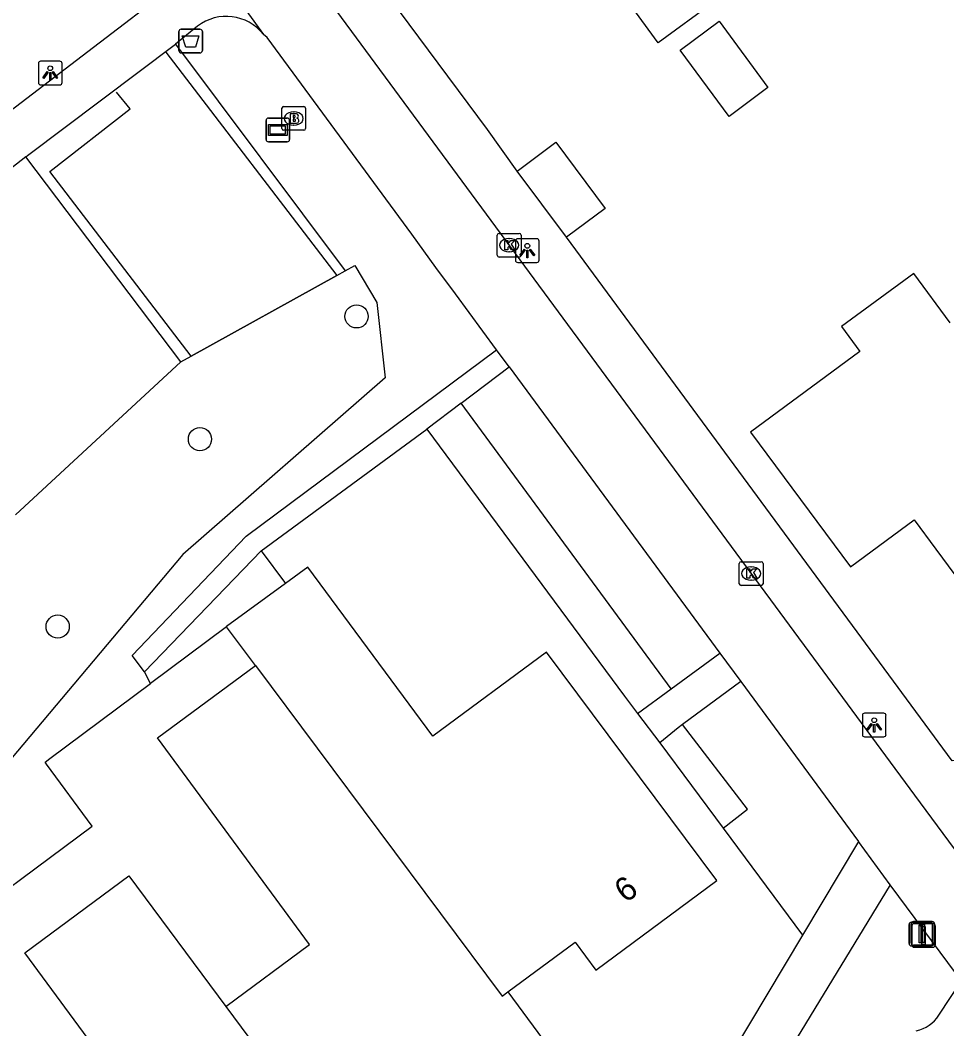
# Model space of a CAD drawing. Extents: x 163427 to 164190, y 380331 to 381641.
# Drawn here: x 163878.34 to 163917.37, y 381059.16 to 381101.66 of the extents above; entities that cross this region are included whole.
import ezdxf

# ---------------------------------------------------------------- set-up
doc = ezdxf.new("R2010")
doc.units = 0
for name, color, linetype in [('IMGEO_Afsluitpaal', 7, 'Continuous'), ('IMGEO_Afvalbak', 7, 'Continuous'), ('IMGEO_Boom', 7, 'Continuous'), ('IMGEO_Brandkraan', 7, 'Continuous'), ('IMGEO_Fietspad_open', 7, 'Continuous'), ('IMGEO_Groenvoorziening', 7, 'Continuous'), ('IMGEO_Hek', 7, 'Continuous'), ('IMGEO_Kolk', 7, 'Continuous'), ('IMGEO_Lichtpunt', 7, 'Continuous'), ('IMGEO_Muur', 7, 'Continuous'), ('IMGEO_Pand', 7, 'Continuous'), ('IMGEO_Pand_nummerreeks', 7, 'Continuous'), ('IMGEO_Verklikker', 7, 'Continuous'), ('IMGEO_Voetpad_halfverhard', 7, 'Continuous'), ('IMGEO_Voetpad_open', 7, 'Continuous')]:
    doc.layers.add(name, color=color, linetype=linetype)

msp = doc.modelspace()

# ---------------------------------------------------------------- linework, layer by layer
at = {"layer": 'IMGEO_Afsluitpaal'}
for p, q in [((163915.959, 381063.681), (163916.749, 381063.681)), ((163916.749, 381063.681), (163915.959, 381063.681)), ((163915.778, 381062.756), (163915.778, 381063.556)), ((163915.778, 381063.556), (163915.778, 381062.756)), ((163915.859, 381062.781), (163915.859, 381063.581)), ((163915.859, 381063.581), (163915.859, 381062.781)), ((163915.878, 381063.656), (163916.668, 381063.656)), ((163916.668, 381063.656), (163915.878, 381063.656)), ((163915.887, 381062.696), (163915.887, 381063.496)), ((163915.887, 381063.496), (163915.887, 381062.696)), ((163915.987, 381063.596), (163916.777, 381063.596)), ((163916.777, 381063.596), (163915.987, 381063.596)), ((163916.768, 381063.556), (163916.768, 381062.756)), ((163916.768, 381062.756), (163916.768, 381063.556)), ((163916.849, 381063.581), (163916.849, 381062.781)), ((163916.849, 381062.781), (163916.849, 381063.581)), ((163916.877, 381063.496), (163916.877, 381062.696)), ((163916.877, 381062.696), (163916.877, 381063.496)), ((163916.668, 381062.656), (163915.878, 381062.656)), ((163915.878, 381062.656), (163916.668, 381062.656)), ((163916.749, 381062.681), (163915.959, 381062.681)), ((163915.959, 381062.681), (163916.749, 381062.681)), ((163916.777, 381062.596), (163915.987, 381062.596)), ((163915.987, 381062.596), (163916.777, 381062.596))]:
    msp.add_line(p, q, dxfattribs=at)
for points in [[(163916.198, 381063.531), (163916.348, 381063.531), (163916.348, 381062.781), (163916.198, 381062.781), (163916.198, 381063.531)], [(163916.279, 381063.556), (163916.429, 381063.556), (163916.429, 381062.806), (163916.279, 381062.806), (163916.279, 381063.556)], [(163916.307, 381063.471), (163916.457, 381063.471), (163916.457, 381062.721), (163916.307, 381062.721), (163916.307, 381063.471)]]:
    msp.add_lwpolyline(points, dxfattribs=at)
for centre, start, end in [((163915.959, 381063.581), 90, 180), ((163915.959, 381063.581), 90, 180), ((163916.749, 381063.581), 0, 90), ((163916.749, 381063.581), 360, 90), ((163915.878, 381063.556), 90, 180), ((163915.878, 381063.556), 90, 180), ((163915.987, 381063.496), 90, 180), ((163915.987, 381063.496), 90, 180), ((163916.668, 381063.556), 0, 90), ((163916.668, 381063.556), 360, 90), ((163916.777, 381063.496), 0, 90), ((163916.777, 381063.496), 360, 90), ((163915.878, 381062.756), 180, 270), ((163915.878, 381062.756), 180, 270), ((163915.959, 381062.781), 180, 270), ((163915.959, 381062.781), 180, 270), ((163915.987, 381062.696), 180, 270), ((163915.987, 381062.696), 180, 270), ((163916.668, 381062.756), 270, 0), ((163916.668, 381062.756), 270, 0), ((163916.749, 381062.781), 270, 0), ((163916.749, 381062.781), 270, 0), ((163916.777, 381062.696), 270, 0), ((163916.777, 381062.696), 270, 0)]:
    msp.add_arc(centre, 0.1, start, end, dxfattribs=at)
at = {"layer": 'IMGEO_Afvalbak'}
for p, q in [((163885.023, 381100.383), (163885.023, 381101.183)), ((163885.023, 381101.183), (163885.023, 381100.383)), ((163885.123, 381101.283), (163885.913, 381101.283)), ((163885.913, 381101.283), (163885.123, 381101.283)), ((163886.013, 381101.183), (163886.013, 381100.383)), ((163886.013, 381100.383), (163886.013, 381101.183)), ((163885.913, 381100.283), (163885.123, 381100.283)), ((163885.123, 381100.283), (163885.913, 381100.283))]:
    msp.add_line(p, q, dxfattribs=at)
msp.add_lwpolyline([(163885.166, 381100.997), (163885.87, 381100.997), (163885.721, 381100.527), (163885.315, 381100.527), (163885.166, 381100.997)], dxfattribs=at)
for centre, start, end in [((163885.123, 381101.183), 90, 180), ((163885.123, 381101.183), 90, 180), ((163885.913, 381101.183), 0, 90), ((163885.913, 381101.183), 360, 90), ((163885.123, 381100.383), 180, 270), ((163885.123, 381100.383), 180, 270), ((163885.913, 381100.383), 270, 0), ((163885.913, 381100.383), 270, 0)]:
    msp.add_arc(centre, 0.1, start, end, dxfattribs=at)
at = {"layer": 'IMGEO_Boom'}
for centre in [(163892.507, 381089.182), (163885.912, 381084.008), (163879.92, 381076.111)]:
    msp.add_circle(centre, 0.489, dxfattribs=at)
at = {"layer": 'IMGEO_Brandkraan'}
for p, q in [((163889.361, 381097.097), (163889.361, 381097.949)), ((163889.436, 381098.023), (163890.288, 381098.023)), ((163889.849, 381097.803), (163889.874, 381097.803)), ((163890.362, 381097.949), (163890.362, 381097.097)), ((163889.872, 381097.243), (163889.847, 381097.243)), ((163890.288, 381097.023), (163889.436, 381097.023))]:
    msp.add_line(p, q, dxfattribs=at)
for points in [[(163889.361, 381097.097), (163889.361, 381097.949)], [(163889.436, 381098.023), (163890.288, 381098.023)], [(163889.709, 381097.723), (163889.709, 381097.323), (163889.922, 381097.323)], [(163889.94, 381097.723), (163889.709, 381097.723)], [(163890.362, 381097.949), (163890.362, 381097.097)], [(163889.888, 381097.642), (163889.834, 381097.642), (163889.834, 381097.566)], [(163889.834, 381097.566), (163889.887, 381097.566)], [(163889.896, 381097.49), (163889.834, 381097.49), (163889.834, 381097.409)], [(163889.834, 381097.409), (163889.896, 381097.409)], [(163890.288, 381097.023), (163889.436, 381097.023)]]:
    msp.add_lwpolyline(points, dxfattribs=at)
for centre, radius, start, end in [((163889.438, 381097.947), 0.0765, 91.552, 178.448), ((163889.438, 381097.947), 0.0765, 91.552, 178.448), ((163889.944, 381097.578), 0.145, 59.4692, 91.5367), ((163889.969, 381097.625), 0.0922, 285.5137, 58.1501), ((163890.286, 381097.947), 0.0765, 1.552, 88.448), ((163890.286, 381097.947), 0.0765, 1.552, 88.448), ((163889.889, 381097.604), 0.0379, 267.8285, 90.9355), ((163889.897, 381097.449), 0.0404, 269.8759, 90.5077), ((163889.928, 381097.574), 0.251, 268.6676, 293.5347), ((163889.974, 381097.433), 0.105, 301.3115, 78.989), ((163889.438, 381097.099), 0.0765, 181.552, 268.448), ((163889.438, 381097.099), 0.0765, 181.552, 268.448), ((163890.286, 381097.099), 0.0765, 271.552, 358.448), ((163890.286, 381097.099), 0.0765, 271.552, 358.448)]:
    msp.add_arc(centre, radius, start, end, dxfattribs=at)
for centre, major_axis, ratio, start_param, end_param in [((163889.848, 381097.523), (-0.387, 0.002), 0.722429, 4.712389, 7.853982), ((163889.873, 381097.523), (-0.39, 0.002), 0.717154, 1.570796, 4.712389)]:
    msp.add_ellipse(centre, major_axis=major_axis, ratio=ratio, start_param=start_param, end_param=end_param, dxfattribs=at)
at = {"layer": 'IMGEO_Fietspad_open'}
for points in [[(163879.294, 381118.846), (163916.003, 381069.011), (163920.063, 381063.521)], [(163885.203, 381105.739), (163888.584, 381101.063)], [(163898.402, 381087.778), (163896.67, 381090.133), (163895.849, 381091.249), (163894.831, 381092.652), (163888.737, 381100.935), (163888.584, 381101.063)], [(163898.929, 381087.061), (163898.402, 381087.778)], [(163898.929, 381087.061), (163907.808, 381074.986)], [(163907.808, 381074.986), (163908.685, 381073.793)], [(163908.685, 381073.793), (163913.644, 381067.049)], [(163914.985, 381065.235), (163913.644, 381067.049)], [(163917.772, 381061.459), (163914.985, 381065.235)]]:
    msp.add_lwpolyline(points, dxfattribs=at)
at = {"layer": 'IMGEO_Groenvoorziening'}
for points in [[(163884.881, 381100.649), (163892.032, 381091.103)], [(163885.102, 381087.269), (163878.573, 381095.902)], [(163892.032, 381091.103), (163892.433, 381091.325), (163893.363, 381089.769), (163893.712, 381086.589), (163885.188, 381079.149), (163877.401, 381069.894), (163877.35, 381068.327), (163876.539, 381066.473), (163872.253, 381063.156), (163871.244, 381061.59), (163871.684, 381058.886), (163871, 381056.23), (163869.868, 381054.37), (163867.112, 381051.126), (163865.984, 381046.133)], [(163885.102, 381087.269), (163885.54, 381087.511), (163891.682, 381090.91), (163892.032, 381091.103)], [(163878.149, 381080.823), (163885.102, 381087.269)], [(163905.761, 381073.491), (163896.906, 381085.524)], [(163895.465, 381084.429), (163903.796, 381073.179), (163904.337, 381072.452)], [(163888.488, 381079.3), (163889.508, 381077.923)], [(163887.036, 381076.097), (163883.835, 381073.718)], [(163883.835, 381073.718), (163883.575, 381074.205)], [(163877.091, 381056.827), (163873.767, 381061.119), (163873.306, 381061.714), (163874.824, 381062.84), (163881.373, 381067.697), (163879.447, 381070.311), (163879.387, 381070.393), (163879.593, 381070.547), (163883.835, 381073.718)], [(163907.947, 381067.612), (163908.974, 381068.413), (163906.233, 381071.982)], [(163905.279, 381071.208), (163907.947, 381067.612)], [(163907.947, 381067.612), (163911.288, 381063.108)]]:
    msp.add_lwpolyline(points, dxfattribs=at)
at = {"layer": 'IMGEO_Hek'}
for points in [[(163884.476, 381100.317), (163891.682, 381090.91)], [(163885.54, 381087.511), (163879.594, 381095.281), (163882.973, 381097.928), (163882.403, 381098.624)], [(163891.682, 381090.91), (163885.54, 381087.511)]]:
    msp.add_lwpolyline(points, dxfattribs=at)
at = {"layer": 'IMGEO_Kolk'}
for p, q in [((163898.433, 381091.755), (163898.433, 381092.607)), ((163898.508, 381092.681), (163899.36, 381092.681)), ((163899.434, 381092.607), (163899.434, 381091.755)), ((163898.921, 381092.461), (163898.946, 381092.461)), ((163898.944, 381091.901), (163898.919, 381091.901)), ((163899.36, 381091.681), (163898.508, 381091.681)), ((163908.625, 381077.919), (163908.625, 381078.771)), ((163908.7, 381078.845), (163909.552, 381078.845)), ((163909.113, 381078.625), (163909.138, 381078.625)), ((163909.626, 381078.771), (163909.626, 381077.919)), ((163909.552, 381077.845), (163908.7, 381077.845)), ((163909.136, 381078.065), (163909.111, 381078.065))]:
    msp.add_line(p, q, dxfattribs=at)
for points in [[(163898.433, 381091.755), (163898.433, 381092.607)], [(163898.508, 381092.681), (163899.36, 381092.681)], [(163899.434, 381092.607), (163899.434, 381091.755)], [(163898.754, 381092.381), (163898.877, 381092.381), (163898.877, 381092.23), (163899.007, 381092.381), (163899.171, 381092.381), (163899.025, 381092.23), (163899.178, 381091.981), (163899.026, 381091.981), (163898.941, 381092.145), (163898.877, 381092.078), (163898.877, 381091.981), (163898.754, 381091.981), (163898.754, 381092.381)], [(163899.36, 381091.681), (163898.508, 381091.681)], [(163908.625, 381077.919), (163908.625, 381078.771)], [(163908.7, 381078.845), (163909.552, 381078.845)], [(163908.946, 381078.545), (163909.069, 381078.545), (163909.069, 381078.394), (163909.199, 381078.545), (163909.363, 381078.545), (163909.217, 381078.394), (163909.37, 381078.145), (163909.218, 381078.145), (163909.133, 381078.309), (163909.069, 381078.242), (163909.069, 381078.145), (163908.946, 381078.145), (163908.946, 381078.545)], [(163909.626, 381078.771), (163909.626, 381077.919)], [(163909.552, 381077.845), (163908.7, 381077.845)]]:
    msp.add_lwpolyline(points, dxfattribs=at)
for centre, start, end in [((163898.51, 381092.605), 91.552, 178.448), ((163898.51, 381092.605), 91.552, 178.448), ((163899.358, 381092.605), 1.552, 88.448), ((163899.358, 381092.605), 1.552, 88.448), ((163898.51, 381091.757), 181.552, 268.448), ((163898.51, 381091.757), 181.552, 268.448), ((163899.358, 381091.757), 271.552, 358.448), ((163899.358, 381091.757), 271.552, 358.448), ((163908.702, 381078.769), 91.552, 178.448), ((163908.702, 381078.769), 91.552, 178.448), ((163909.55, 381078.769), 1.552, 88.448), ((163909.55, 381078.769), 1.552, 88.448), ((163908.702, 381077.921), 181.552, 268.448), ((163908.702, 381077.921), 181.552, 268.448), ((163909.55, 381077.921), 271.552, 358.448), ((163909.55, 381077.921), 271.552, 358.448)]:
    msp.add_arc(centre, 0.0765, start, end, dxfattribs=at)
for centre, major_axis, ratio, start_param, end_param in [((163898.92, 381092.181), (-0.387, 0.002), 0.722429, 4.712389, 7.853982), ((163898.945, 381092.181), (-0.39, 0.002), 0.717154, 1.570796, 4.712389), ((163909.112, 381078.345), (-0.387, 0.002), 0.722429, 4.712389, 7.853982), ((163909.137, 381078.345), (-0.39, 0.002), 0.717154, 1.570796, 4.712389)]:
    msp.add_ellipse(centre, major_axis=major_axis, ratio=ratio, start_param=start_param, end_param=end_param, dxfattribs=at)
at = {"layer": 'IMGEO_Lichtpunt'}
for p, q in [((163879.107, 381099.839), (163879.107, 381099.032)), ((163879.107, 381099.839), (163879.107, 381099.032)), ((163880.009, 381099.934), (163879.201, 381099.934)), ((163880.009, 381099.934), (163879.201, 381099.934)), ((163880.103, 381099.032), (163880.103, 381099.839)), ((163880.103, 381099.032), (163880.103, 381099.839)), ((163879.201, 381098.938), (163880.009, 381098.938)), ((163879.201, 381098.938), (163880.009, 381098.938)), ((163899.199, 381092.357), (163899.199, 381091.55)), ((163899.199, 381092.357), (163899.199, 381091.55)), ((163900.101, 381092.452), (163899.293, 381092.452)), ((163900.101, 381092.452), (163899.293, 381092.452)), ((163900.195, 381091.55), (163900.195, 381092.357)), ((163900.195, 381091.55), (163900.195, 381092.357)), ((163899.293, 381091.456), (163900.101, 381091.456)), ((163899.293, 381091.456), (163900.101, 381091.456)), ((163913.808, 381072.367), (163913.808, 381071.56)), ((163913.808, 381072.367), (163913.808, 381071.56)), ((163914.71, 381072.462), (163913.902, 381072.462)), ((163914.71, 381072.462), (163913.902, 381072.462)), ((163914.804, 381071.56), (163914.804, 381072.367)), ((163914.804, 381071.56), (163914.804, 381072.367)), ((163913.902, 381071.466), (163914.71, 381071.466)), ((163913.902, 381071.466), (163914.71, 381071.466))]:
    msp.add_line(p, q, dxfattribs=at)
for points in [[(163879.481, 381099.503), (163879.52, 381099.475), (163879.332, 381099.213), (163879.294, 381099.24), (163879.481, 381099.503)], [(163879.583, 381099.455), (163879.63, 381099.455), (163879.63, 381099.133), (163879.583, 381099.133), (163879.583, 381099.455)], [(163879.693, 381099.475), (163879.731, 381099.502), (163879.918, 381099.24), (163879.879, 381099.212), (163879.693, 381099.475)], [(163899.573, 381092.021), (163899.612, 381091.993), (163899.424, 381091.731), (163899.386, 381091.758), (163899.573, 381092.021)], [(163899.675, 381091.973), (163899.722, 381091.973), (163899.722, 381091.651), (163899.675, 381091.651), (163899.675, 381091.973)], [(163899.785, 381091.993), (163899.823, 381092.02), (163900.01, 381091.758), (163899.971, 381091.73), (163899.785, 381091.993)], [(163914.182, 381072.031), (163914.221, 381072.003), (163914.033, 381071.741), (163913.995, 381071.768), (163914.182, 381072.031)], [(163914.284, 381071.983), (163914.331, 381071.983), (163914.331, 381071.661), (163914.284, 381071.661), (163914.284, 381071.983)], [(163914.394, 381072.003), (163914.432, 381072.03), (163914.619, 381071.768), (163914.58, 381071.74), (163914.394, 381072.003)]]:
    msp.add_lwpolyline(points, dxfattribs=at)
for centre in [(163879.606, 381099.637), (163899.698, 381092.155), (163914.307, 381072.165)]:
    msp.add_circle(centre, 0.0994, dxfattribs=at)
for centre, start, end in [((163879.201, 381099.839), 90, 180), ((163879.201, 381099.839), 90, 180), ((163880.009, 381099.839), 0, 90), ((163880.009, 381099.839), 0, 90), ((163879.201, 381099.032), 180, 270), ((163879.201, 381099.032), 180, 270), ((163880.009, 381099.032), 270, 0), ((163880.009, 381099.032), 270, 360), ((163899.293, 381092.357), 90, 180), ((163899.293, 381092.357), 90, 180), ((163900.101, 381092.357), 0, 90), ((163900.101, 381092.357), 0, 90), ((163899.293, 381091.55), 180, 270), ((163899.293, 381091.55), 180, 270), ((163900.101, 381091.55), 270, 0), ((163900.101, 381091.55), 270, 360), ((163913.902, 381072.367), 90, 180), ((163913.902, 381072.367), 90, 180), ((163914.71, 381072.367), 0, 90), ((163914.71, 381072.367), 0, 90), ((163913.902, 381071.56), 180, 270), ((163913.902, 381071.56), 180, 270), ((163914.71, 381071.56), 270, 0), ((163914.71, 381071.56), 270, 360)]:
    msp.add_arc(centre, 0.0946, start, end, dxfattribs=at)
at = {"layer": 'IMGEO_Muur'}
for points in [[(163899.274, 381095.308), (163898.019, 381097.05)], [(163917.592, 381070.453), (163901.342, 381092.521)]]:
    msp.add_lwpolyline(points, dxfattribs=at)
at = {"layer": 'IMGEO_Pand'}
for points in [[(163907.553, 381102.419), (163905.209, 381100.711), (163902.5, 381104.428), (163904.843, 381106.137), (163907.553, 381102.419)], [(163909.832, 381098.821), (163908.202, 381097.611), (163906.134, 381100.398), (163907.775, 381101.616), (163909.832, 381098.821)], [(163899.274, 381095.308), (163900.905, 381096.518), (163902.973, 381093.731), (163901.342, 381092.521)], [(163901.342, 381092.521), (163899.274, 381095.308)], [(163917.51, 381088.914), (163915.971, 381090.994), (163912.93, 381088.749), (163913.702, 381087.703), (163909.096, 381084.301), (163913.308, 381078.634), (163915.996, 381080.615), (163916.909, 381079.376), (163919.581, 381075.75), (163920.064, 381076.108), (163920.487, 381075.538), (163923.01, 381077.406), (163922.587, 381077.976), (163924.565, 381079.44), (163924.111, 381080.059)], [(163898.873, 381060.714), (163901.712, 381062.813), (163902.58, 381061.639), (163907.678, 381065.409), (163900.503, 381075.038), (163895.72, 381071.499), (163890.456, 381078.613), (163889.508, 381077.923)], [(163889.508, 381077.923), (163887.023, 381076.115), (163887.036, 381076.097)], [(163888.254, 381074.465), (163887.036, 381076.097)], [(163887.001, 381060.106), (163890.529, 381062.715), (163884.124, 381071.429), (163888.254, 381074.465)], [(163888.254, 381074.465), (163898.641, 381060.542), (163898.873, 381060.714)], [(163881.446, 381050.999), (163884.971, 381053.633), (163878.533, 381062.366), (163882.919, 381065.608), (163887.001, 381060.106)], [(163898.873, 381060.714), (163901.4, 381057.297), (163901.127, 381057.095), (163900.502, 381057.939), (163898.13, 381056.185), (163899.498, 381054.336), (163897.025, 381052.521), (163896.078, 381053.811), (163893.224, 381051.717)], [(163887.001, 381060.106), (163893.224, 381051.717)]]:
    msp.add_lwpolyline(points, dxfattribs=at)
at = {"layer": 'IMGEO_Verklikker'}
for p, q in [((163888.694, 381096.637), (163888.694, 381097.437)), ((163888.694, 381097.437), (163888.694, 381096.637)), ((163888.794, 381097.537), (163889.584, 381097.537)), ((163889.584, 381097.537), (163888.794, 381097.537)), ((163889.684, 381097.437), (163889.684, 381096.637)), ((163889.684, 381096.637), (163889.684, 381097.437)), ((163889.584, 381096.537), (163888.794, 381096.537)), ((163888.794, 381096.537), (163889.584, 381096.537))]:
    msp.add_line(p, q, dxfattribs=at)
for points in [[(163888.795, 381097.269), (163889.583, 381097.269), (163889.583, 381096.805), (163888.795, 381096.805), (163888.795, 381097.269)], [(163888.86, 381097.204), (163888.86, 381096.87), (163889.518, 381096.87), (163889.518, 381097.204), (163888.86, 381097.204)]]:
    msp.add_lwpolyline(points, dxfattribs=at)
for centre, start, end in [((163888.794, 381097.437), 90, 180), ((163888.794, 381097.437), 90, 180), ((163889.584, 381097.437), 0, 90), ((163889.584, 381097.437), 360, 90), ((163888.794, 381096.637), 180, 270), ((163888.794, 381096.637), 180, 270), ((163889.584, 381096.637), 270, 0), ((163889.584, 381096.637), 270, 0)]:
    msp.add_arc(centre, 0.1, start, end, dxfattribs=at)
at = {"layer": 'IMGEO_Voetpad_halfverhard'}
for points in [[(163860.665, 381084.431), (163863.932, 381087.182), (163869.42, 381091.331), (163875.557, 381096.043), (163881.424, 381100.523), (163884.816, 381103.12)], [(163885.813, 381101.41), (163884.881, 381100.649)], [(163878.573, 381095.902), (163878.655, 381095.966), (163884.881, 381100.649)], [(163878.573, 381095.902), (163872.498, 381091.145), (163864.015, 381084.713)]]:
    msp.add_lwpolyline(points, dxfattribs=at)
msp.add_arc((163887.024, 381099.846), 1.978, 37.9623, 127.7622, dxfattribs=at)
at = {"layer": 'IMGEO_Voetpad_open'}
for points in [[(163899.274, 381095.308), (163898.019, 381097.05), (163882.295, 381118.226)], [(163952.531, 381076.448), (163917.592, 381070.453), (163901.342, 381092.521)], [(163883.575, 381074.205), (163883.054, 381074.889), (163887.858, 381079.918), (163898.402, 381087.778)], [(163896.906, 381085.524), (163898.929, 381087.061)], [(163896.906, 381085.524), (163895.465, 381084.429)], [(163888.488, 381079.3), (163895.465, 381084.429)], [(163883.575, 381074.205), (163888.488, 381079.3)], [(163905.761, 381073.491), (163907.808, 381074.986)], [(163904.337, 381072.452), (163905.761, 381073.491)], [(163908.685, 381073.793), (163906.233, 381071.982)], [(163904.337, 381072.452), (163905.279, 381071.208)], [(163906.233, 381071.982), (163906.055, 381071.85), (163905.279, 381071.208)], [(163913.644, 381067.049), (163911.288, 381063.108)], [(163914.985, 381065.235), (163908.438, 381054.481), (163910.058, 381053.502)], [(163911.288, 381063.108), (163897.12, 381039.404), (163884.702, 381018.618)], [(163917.023, 381059.738), (163917.978, 381061.179), (163917.772, 381061.459)]]:
    msp.add_lwpolyline(points, dxfattribs=at)
msp.add_arc((163915.771, 381060.523), 1.478, 282.115, 327.918, dxfattribs=at)

# ---------------------------------------------------------------- texts
at = {"layer": 'IMGEO_Pand_nummerreeks'}
msp.add_text('6', height=1, rotation=36.486, dxfattribs=at).set_placement((163903.84, 381064.437))

doc.saveas('drawing.dxf')
